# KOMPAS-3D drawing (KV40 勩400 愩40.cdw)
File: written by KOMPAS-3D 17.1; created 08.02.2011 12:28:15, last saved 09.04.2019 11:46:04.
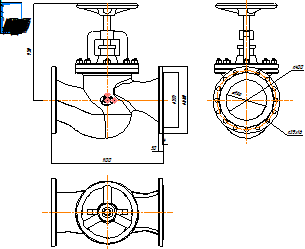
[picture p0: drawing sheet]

Title block, sheet 1: name: KV 40 Ду400; material: Внимание! Данный продукт является объектом авторского права ООО «Торговый Дом АДЛ». / Запрещается изменение, копирование, распространение / (в том числе путем копирования на другие сайты и ресурсы в Интернете) / или любое иное использование информации и объектов без предварительного / согласия правообладателя (ООО «Торговый Дом АДЛ»).; scale: 1:1; sheets: 1; organisation: ООО "Торговый дом АДЛ"; sheet format: A4; stored path: \\adlc.lan\data\АДЛ_ПКД\3D-модели\ADL production\Вентили ГРАНВЕНТ\KV40\KOMPAS 2D\KV 40 Ду400.cdw

Views: Спереди 1, Проекционный вид 2, Проекционный вид 3
Dimensions and other numbers on the sheet: 950; 1100; 4; 50; 535; 660; 400; 39; 1:1; 1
